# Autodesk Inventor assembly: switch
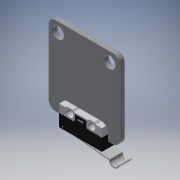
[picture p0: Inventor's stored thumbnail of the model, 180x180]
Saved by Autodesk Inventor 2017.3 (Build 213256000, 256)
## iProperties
Part Number: switch
Material: Générique
Document SubType Name: Assembly
Designer: ficho
Author: ficho
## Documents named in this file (3)
- G:\travail\année 2019-2020\réforme\avant février\IT\switch.iam
- G:\travail\année 2019-2020\réforme\avant février\IT\DM1-02P.ipt
- C:\Users\ficho\OneDrive\Documents\plaque.ipt
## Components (2 placed, 2 different names)
1. DM1-02P:1 — Affleurement:1
2. plaque:1 — Affleurement:1
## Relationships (1: Flush 1)
- Affleurement:1 [Flush]: DM1-02P:1 ↔ plaque:1
